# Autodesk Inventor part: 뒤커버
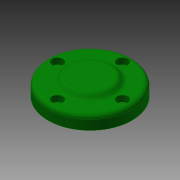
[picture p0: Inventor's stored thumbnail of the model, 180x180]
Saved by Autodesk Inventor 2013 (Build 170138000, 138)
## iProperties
Created: 2015-09
Part Number: 뒤커버
Material: 알루미늄 6061
Document SubType Name: Modeling
Designer: mduedu
Density: 1 g/cm^3
Author: mduedu
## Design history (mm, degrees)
sketch "스케치1"
  geometry: L1 (0, 9)-(0, -9); L2 (0, 9)-(15, 9); L3 (15, 9)-(18, 6); L4 (18, 6)-(31, 6); L5 (31, 6)-(31, -4); L6 (31, -4)-(17.5, -4); L7 (17.5, -4)-(17.5, -9); L8 (17.5, -9)-(0, -9); 2 further points
  constraints: 16 end point, 3 parallel, 2 perpendicular, 1 coincident, 1 horizontal, 1 midpoint, 1 vertical
  dimensions: "d1" = 3 distance between parallel lines of L4 L2; "d2" = 10 distance of L4.end L5.end; "d3" = 36 diameter of L3.end L1; "d4" = 35 diameter of L7 L1; "d5" = 62 diameter of L5 L1; "d7" = 45 deg angle of L3 L5; "d48" = 5 distance between parallel lines of L6 L8
revolve "회전1" sketch "스케치1" stored, may be unused: angle "d8" = 90 deg
hole "구멍1" diameter "d11" = 30; stored, may be unused: countersink angle "d15" = 90 deg, drill point angle "d17" = 0 deg; dims "d12" = 6, "d13" = 4, "d14" = 2, "d16" = 10, "d49" = 10, "d50" = 10
fillet "모깎기1" dims "d18" = 3
fillet "모깎기2" dims "d25" = 3
fillet "모깎기3" dims "d26" = 3
sketch "스케치3"
  geometry: 4 further points
hole "구멍2" sketch "스케치3" at (-24, 0), (0, -24), (24, 0), (0, 24) diameter "d35" = 4.5; stored, may be unused: countersink angle "d39" = 90 deg, drill point angle "d41" = 0 deg; dims "d36" = 6, "d37" = 8, "d38" = 4.6, "d40" = 8
chamfer "모따기3" distance "d42" = 1; stored, may be unused: second distance "d43" = 2, angle "d44" = 45 deg
fillet "모깎기4" dims "d45" = 3
node "솔리드1"
sketch "스케치2" dims "d27" = 48
  geometry: 6 further points
  constraints: 2 vertical alignment, 1 coincident, 7 other
  dimensions: "d33" = 360 deg dimension on point (0, 0) point (0, 24) (derived)
